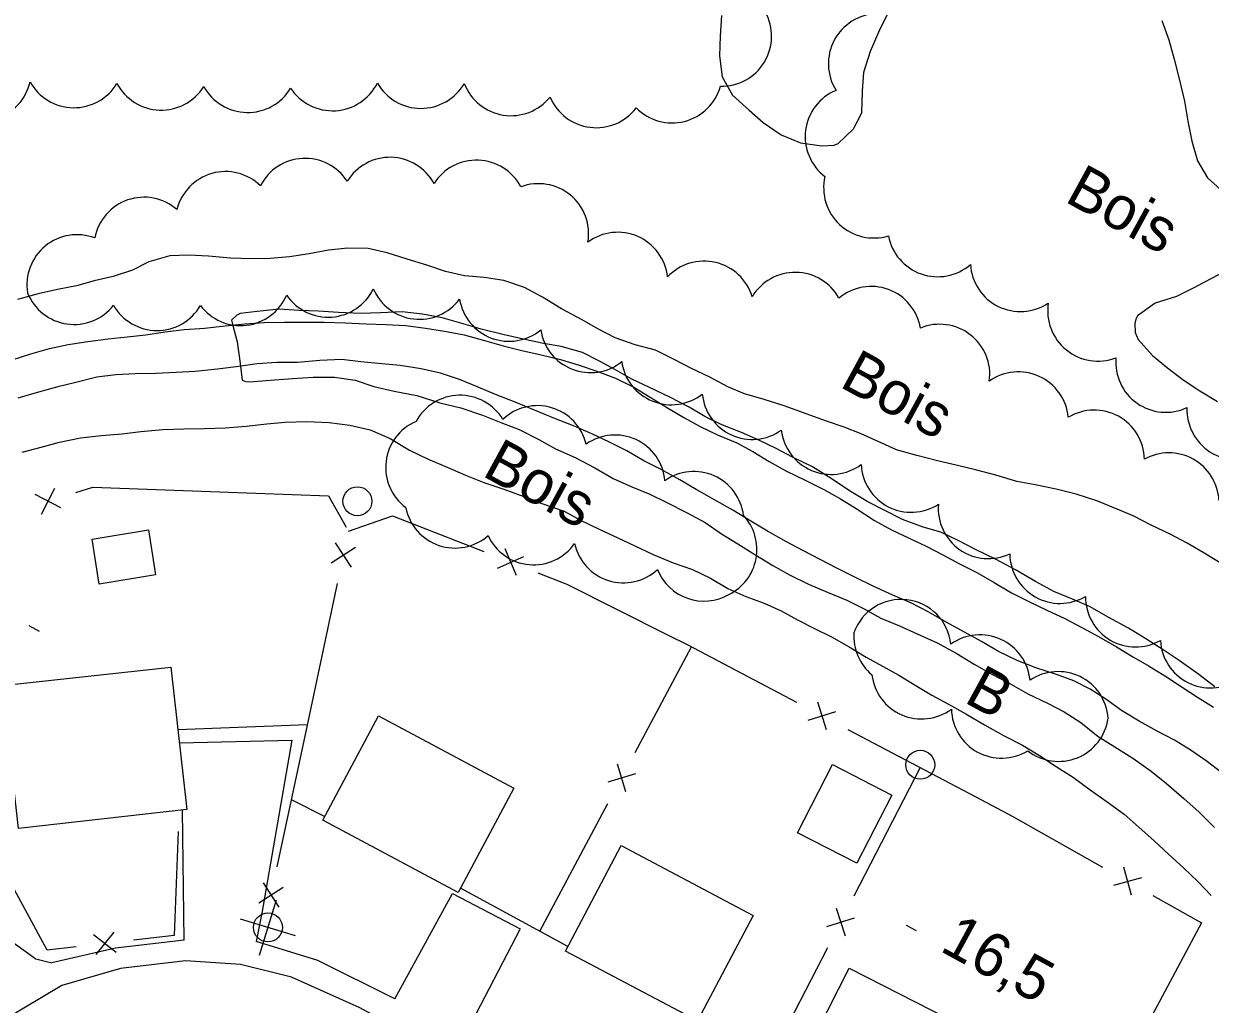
# Model space of a CAD drawing. Extents: x 219136 to 222520, y 5421589 to 5424530.
# Drawn here: x 220486.7 to 220568.6, y 5424061.3 to 5424129 of the extents above; entities that cross this region are included whole.
import ezdxf

# ---------------------------------------------------------------- set-up
doc = ezdxf.new("R2010")
doc.units = 0
for name, color, linetype in [('Level 19', 7, 'Continuous'), ('Level 2', 7, 'Continuous'), ('Level 21', 7, 'Continuous'), ('Level 3', 7, 'Continuous'), ('Level 31', 7, 'Continuous'), ('Level 36', 7, 'Continuous'), ('Level 37', 7, 'Continuous'), ('Level 4', 7, 'Continuous'), ('Level 44', 7, 'Continuous')]:
    doc.layers.add(name, color=color, linetype=linetype)

msp = doc.modelspace()

# ---------------------------------------------------------------- linework, layer by layer
at = {"layer": 'Level 19'}
for points in [[(220497.41, 5424079.37), (220505.18, 5424079.54), (220503.11, 5424067.61), (220502.72, 5424065.65)], [(220497.74, 5424065.73), (220497.63, 5424074.72)], [(220476.48, 5424066.51), (220479.86, 5424069.94), (220487.5, 5424064.45), (220488.59, 5424064.17)], [(220512.29, 5424061.68), (220516.28, 5424068.95), (220520.94, 5424066.53), (220517.29, 5424059.47)]]:
    msp.add_lwpolyline(points, dxfattribs=at)
at = {"layer": 'Level 2'}
for points in [[(220534.85, 5424129.57), (220534.75, 5424128.14), (220534.71, 5424126.8), (220534.9, 5424125.34), (220535.62, 5424124.07), (220536.76, 5424123.05), (220537.73, 5424122.19), (220538.97, 5424121.33), (220540.31, 5424120.78), (220541.79, 5424120.58), (220542.64, 5424120.62), (220542.91, 5424120.73), (220543.98, 5424121.74), (220544.55, 5424122.86), (220544.58, 5424124.36), (220544.68, 5424125.67), (220545.14, 5424127.11), (220545.74, 5424128.49), (220546.3, 5424129.61)], [(220565.27, 5424129.24), (220565.74, 5424127.89), (220566.11, 5424126.55), (220566.48, 5424125.12), (220566.83, 5424123.67), (220567.07, 5424122.27), (220567.33, 5424120.89), (220567.72, 5424119.53), (220568.43, 5424118.36), (220569.52, 5424117.38), (220570.52, 5424116.47), (220571.53, 5424115.73), (220572.04, 5424115.08), (220572.11, 5424114.81), (220572.12, 5424114.49), (220571.77, 5424113.28), (220571.34, 5424112.8), (220571, 5424112.63), (220569.84, 5424112.02), (220568.66, 5424111.4)], [(220553.79, 5424097.84), (220552.4, 5424098.22), (220551.15, 5424098.51), (220549.76, 5424098.83), (220548.34, 5424099.19), (220546.94, 5424099.6), (220545.68, 5424100.16), (220544.51, 5424100.7), (220543.32, 5424101.15), (220542.11, 5424101.58), (220540.69, 5424102.08), (220539.26, 5424102.6), (220537.8, 5424103.06), (220536.45, 5424103.45), (220535.29, 5424103.94), (220534.05, 5424104.61), (220532.78, 5424105.2), (220531.59, 5424105.83), (220530.29, 5424106.46), (220528.88, 5424106.85), (220527.5, 5424107.32), (220526.32, 5424107.94), (220525.22, 5424108.56), (220523.81, 5424109.32), (220522.49, 5424110.12), (220521.24, 5424110.79), (220519.81, 5424111.29), (220518.45, 5424111.49), (220517.11, 5424111.6), (220515.79, 5424111.89), (220514.49, 5424112.34), (220513.15, 5424112.76), (220511.77, 5424113.19), (220510.44, 5424113.49), (220509.04, 5424113.51), (220507.7, 5424113.37), (220506.37, 5424113.11), (220505.01, 5424112.92), (220503.68, 5424112.81), (220502.36, 5424112.77), (220500.95, 5424112.82), (220499.42, 5424112.95), (220498.06, 5424113.03), (220496.75, 5424112.98), (220495.31, 5424112.58), (220494.18, 5424111.99), (220492.83, 5424111.55), (220491.52, 5424111.25), (220490.31, 5424110.92), (220489, 5424110.66), (220487.65, 5424110.37), (220486.22, 5424109.97)], [(220568.66, 5424111.4), (220567.47, 5424110.78), (220566.27, 5424110.17), (220564.8, 5424109.71), (220563.58, 5424108.83), (220563.47, 5424108.6), (220563.4, 5424108.32), (220563.42, 5424107.7), (220563.64, 5424107.21), (220564.62, 5424106.11), (220565.66, 5424105.24), (220566.73, 5424104.42), (220567.9, 5424103.66), (220569.12, 5424102.93)], [(220552.39, 5424092.71), (220551.19, 5424093.32), (220550.01, 5424093.91), (220548.78, 5424094.25), (220547.36, 5424094.77), (220546.08, 5424095.43), (220544.96, 5424096), (220543.69, 5424096.76), (220542.42, 5424097.61), (220541.14, 5424098.42), (220539.75, 5424099.09), (220538.62, 5424099.69), (220537.42, 5424100.26), (220536.23, 5424100.78), (220534.83, 5424101.34), (220533.7, 5424101.88), (220532.62, 5424102.54), (220531.29, 5424103.23), (220529.88, 5424103.9), (220528.67, 5424104.46), (220527.54, 5424105.12), (220526.37, 5424105.74), (220525.25, 5424106.32), (220523.78, 5424106.73), (220522.55, 5424106.93), (220521.17, 5424107.23), (220519.75, 5424107.56), (220518.26, 5424107.92), (220516.86, 5424108.34), (220515.56, 5424108.7), (220514.21, 5424108.96), (220512.79, 5424109.12), (220511.29, 5424109.04), (220509.92, 5424109), (220508.39, 5424109.07), (220507.02, 5424109.16), (220505.69, 5424109.22), (220504.3, 5424109.29), (220502.78, 5424109.14), (220501.61, 5424109), (220501.38, 5424108.88), (220501.01, 5424108.54), (220501.08, 5424108.27), (220501.4, 5424107.04), (220501.6, 5424105.54), (220501.74, 5424104.39), (220501.99, 5424104.3), (220502.27, 5424104.29), (220503.69, 5424104.39), (220505.23, 5424104.52), (220506.66, 5424104.6), (220508.13, 5424104.6), (220509.56, 5424104.39), (220510.85, 5424103.97), (220512.25, 5424103.63), (220513.81, 5424103.35), (220515.4, 5424102.84), (220516.84, 5424102.48), (220518.34, 5424101.98), (220519.61, 5424101.48), (220520.87, 5424101), (220522.23, 5424100.3), (220523.39, 5424099.67), (220524.74, 5424099.06), (220526.1, 5424098.34)], [(220494.75, 5424100.85), (220496.27, 5424100.99), (220497.72, 5424101.05), (220499.14, 5424101.06), (220500.6, 5424101.12), (220502.03, 5424101.23), (220503.46, 5424101.38), (220504.72, 5424101.49), (220506.22, 5424101.55), (220507.75, 5424101.47), (220509.19, 5424101.3), (220510.59, 5424100.98), (220511.96, 5424100.37), (220513.3, 5424099.57), (220514.59, 5424098.94), (220515.91, 5424098.4), (220517.17, 5424097.84), (220518.43, 5424097.34), (220519.83, 5424096.87), (220521.21, 5424096.36), (220522.44, 5424095.89), (220523.98, 5424095.35), (220525.17, 5424094.72), (220526.41, 5424094.12), (220527.7, 5424093.51), (220528.86, 5424092.96), (220530.14, 5424092.37), (220531.51, 5424091.79), (220532.84, 5424091.33), (220534.1, 5424090.74), (220535.3, 5424090.02), (220536.54, 5424089.46), (220537.8, 5424089), (220538.97, 5424088.48), (220540.1, 5424087.86), (220541.24, 5424087.28), (220542.45, 5424086.68), (220543.68, 5424085.98), (220544.85, 5424085.28), (220545.98, 5424084.66), (220547.1, 5424084.04), (220548.24, 5424083.35), (220549.39, 5424082.66), (220550.54, 5424082.03), (220551.73, 5424081.36), (220553.01, 5424080.6), (220554.34, 5424079.88), (220555.64, 5424079.21), (220556.81, 5424078.48), (220557.97, 5424077.72), (220559.16, 5424076.96), (220560.32, 5424076.11), (220561.49, 5424075.29), (220562.66, 5424074.43), (220563.71, 5424073.51), (220564.72, 5424072.62), (220565.73, 5424071.67), (220566.78, 5424070.7), (220567.75, 5424069.78), (220568.68, 5424068.82)], [(220486.55, 5424099.42), (220487.87, 5424099.78), (220489.12, 5424100.11), (220490.58, 5424100.41), (220492.04, 5424100.57), (220493.45, 5424100.7), (220494.75, 5424100.85)], [(220526.1, 5424098.34), (220527.38, 5424097.61), (220528.65, 5424097.03), (220529.91, 5424096.54), (220531.04, 5424095.98), (220532.48, 5424095.25), (220533.73, 5424094.57), (220534.85, 5424093.8), (220535.99, 5424093.1), (220537.15, 5424092.37), (220538.4, 5424091.61), (220539.55, 5424090.96), (220540.87, 5424090.31), (220542.23, 5424089.73), (220543.51, 5424089.22), (220544.65, 5424088.63), (220545.85, 5424087.98), (220547.15, 5424087.43), (220548.36, 5424086.89), (220549.74, 5424086.26), (220551.07, 5424085.56), (220552.3, 5424084.79), (220553.52, 5424084.1), (220554.71, 5424083.48), (220556.02, 5424082.75), (220557.38, 5424082.1), (220558.53, 5424081.5), (220559.66, 5424080.77), (220560.87, 5424079.8), (220562.02, 5424079.08), (220563.27, 5424078.31), (220564.53, 5424077.4), (220565.58, 5424076.55), (220566.78, 5424075.51), (220567.85, 5424074.57), (220568.9, 5424073.52)], [(220569.37, 5424091.74), (220568.13, 5424092.5), (220567.02, 5424093.15), (220565.89, 5424093.74), (220564.49, 5424094.42), (220563.34, 5424095), (220562.19, 5424095.49), (220560.78, 5424096.07), (220559.35, 5424096.54), (220557.96, 5424096.87), (220556.51, 5424097.18), (220555.25, 5424097.41), (220553.79, 5424097.84)], [(220568.93, 5424083.23), (220567.82, 5424084.07), (220566.47, 5424085.04), (220565.35, 5424085.79), (220564.17, 5424086.55), (220562.96, 5424087.27), (220561.61, 5424088.01), (220560.27, 5424088.78), (220559.1, 5424089.28), (220557.8, 5424089.8), (220556.53, 5424090.49), (220555.17, 5424091.31), (220553.82, 5424092.02), (220552.39, 5424092.71)]]:
    msp.add_lwpolyline(points, dxfattribs=at)
at = {"layer": 'Level 21'}
for points in [[(220497.74, 5424065.73), (220492.99, 5424065.19), (220488.59, 5424064.17)], [(220512.29, 5424061.68), (220506.97, 5424064.33), (220502.72, 5424065.65)], [(220553.81, 5424039.07), (220553.73, 5424039.04), (220551.84, 5424039.1), (220549.83, 5424039.83), (220547.23, 5424041.1), (220509.83, 5424061.1), (220505.16, 5424063.19), (220501.63, 5424064.07), (220497.84, 5424064.31), (220493.34, 5424063.78), (220489.3, 5424062.62), (220485.23, 5424060.19), (220482.14, 5424057.35), (220479.4, 5424053.9), (220476.93, 5424049.58), (220459.72, 5424016.93), (220442.62, 5423984.31), (220432.48, 5423964.99)]]:
    msp.add_lwpolyline(points, dxfattribs=at)
at = {"layer": 'Level 3'}
for p, q in [((220487.02, 5424087.46), (220487.72, 5424087.08)), ((220547.61, 5424066.78), (220548.3, 5424066.4))]:
    msp.add_line(p, q, dxfattribs=at)
at = {"layer": 'Level 31'}
for points in [[(220495.77, 5424090.95), (220491.88, 5424090.32), (220491.38, 5424093.43), (220495.27, 5424094.06)], [(220485.2, 5424083.31), (220496.83, 5424084.59), (220497.92, 5424074.75), (220486.29, 5424073.46)], [(220511.16, 5424081.22), (220520.51, 5424076.23), (220516.66, 5424069.03), (220507.32, 5424074.02)], [(220540.1, 5424073.16), (220542.52, 5424077.86), (220546.62, 5424075.74), (220544.19, 5424071.05)], [(220533.2, 5424060.17), (220524.07, 5424064.99), (220527.92, 5424072.27), (220537.04, 5424067.45)], [(220549.09, 5424051.8), (220539.93, 5424056.46), (220543.67, 5424063.8), (220552.83, 5424059.13)]]:
    msp.add_lwpolyline(points, close=True, dxfattribs=at)
at = {"layer": 'Level 36'}
for p, q in [((220502.94, 5424064.71), (220504.11, 5424068.52)), ((220505.43, 5424066.03), (220501.62, 5424067.2))]:
    msp.add_line(p, q, dxfattribs=at)
for centre in [(220509.704, 5424096.037), (220548.584, 5424077.847), (220503.527, 5424066.623)]:
    msp.add_circle(centre, 1, dxfattribs=at)
at = {"layer": 'Level 37'}
for p, q in [((220487.88, 5424095.16), (220488.81, 5424096.94)), ((220489.23, 5424095.58), (220487.46, 5424096.51)), ((220507.89, 5424091.78), (220509.57, 5424092.87)), ((220508.18, 5424093.17), (220509.27, 5424091.49)), ((220519.38, 5424091.43), (220521.21, 5424092.23)), ((220520.7, 5424090.91), (220519.9, 5424092.75)), ((220542.1, 5424080.27), (220541.51, 5424082.18)), ((220540.85, 5424080.93), (220542.76, 5424081.52)), ((220528.25, 5424075.98), (220527.66, 5424077.9)), ((220528.91, 5424077.23), (220527, 5424076.65)), ((220563.18, 5424068.84), (220562.64, 5424070.77)), ((220561.95, 5424069.53), (220563.88, 5424070.07)), ((220502.89, 5424068.31), (220504.57, 5424069.4)), ((220503.19, 5424069.69), (220504.28, 5424068.01)), ((220542.78, 5424067.94), (220543.39, 5424066.03)), ((220542.13, 5424066.68), (220544.04, 5424067.29)), ((220491.48, 5424066.14), (220493.05, 5424064.9)), ((220492.89, 5424066.3), (220491.64, 5424064.74))]:
    msp.add_line(p, q, dxfattribs=at)
for points in [[(220490.26, 5424096.64), (220491.43, 5424097.01), (220500.19, 5424096.69)], [(220500.19, 5424096.69), (220507.71, 5424096.41), (220508.92, 5424094.25)], [(220509.08, 5424093.97), (220512.14, 5424095.03), (220518.43, 5424092.56)], [(220508.31, 5424090.37), (220506.23, 5424080.59)], [(220522.16, 5424091.1), (220524.17, 5424090.31), (220531.18, 5424086.8)], [(220531.18, 5424086.8), (220532.48, 5424086.15), (220540.04, 5424082.16)], [(220528.9, 5424078.7), (220532.78, 5424085.99)], [(220506.23, 5424080.6), (220497.31, 5424080.26)], [(220506.23, 5424080.59), (220504.15, 5424070.81)], [(220543.58, 5424080.29), (220552.42, 5424075.63)], [(220548.57, 5424077.66), (220544, 5424068.77)], [(220552.42, 5424075.63), (220554.97, 5424074.28), (220561.17, 5424070.79)], [(220505.14, 5424075.46), (220507.45, 5424074.27)], [(220522.31, 5424066.35), (220527.01, 5424075.17)], [(220497.33, 5424073.25), (220497.05, 5424066.07), (220494.25, 5424065.75)], [(220490.28, 5424065.29), (220488.27, 5424065.06), (220484.46, 5424072.07)], [(220524.24, 5424065.3), (220516.82, 5424069.33)], [(220564.65, 5424068.82), (220568.01, 5424066.93), (220565.11, 5424061.51)], [(220542.17, 5424065.21), (220538.38, 5424057.84)], [(220565.11, 5424061.51), (220560.38, 5424052.7)]]:
    msp.add_lwpolyline(points, dxfattribs=at)
at = {"layer": 'Level 4'}
for points in [[(220485.87, 5424105.81), (220487.16, 5424106.21), (220488.44, 5424106.59), (220489.73, 5424106.86), (220491.09, 5424107.08), (220492.48, 5424107.25), (220493.8, 5424107.39), (220495.1, 5424107.54), (220496.42, 5424107.73), (220497.75, 5424107.89), (220499.14, 5424107.99), (220500.58, 5424108.15), (220501.94, 5424108.28), (220503.27, 5424108.38), (220504.67, 5424108.41), (220506.05, 5424108.41), (220507.4, 5424108.41), (220508.85, 5424108.36), (220510.3, 5424108.29), (220511.68, 5424108.24), (220513.05, 5424108.17), (220514.41, 5424108), (220515.73, 5424107.79), (220517.08, 5424107.54), (220518.49, 5424107.14), (220519.77, 5424106.77), (220521.06, 5424106.45), (220522.4, 5424106.15), (220523.74, 5424105.82), (220525.02, 5424105.44), (220526.24, 5424105.01), (220527.54, 5424104.54), (220528.8, 5424103.91), (220529.92, 5424103.23), (220531.13, 5424102.48), (220532.24, 5424101.83), (220533.38, 5424101.19), (220534.63, 5424100.6), (220535.91, 5424100.07), (220537.02, 5424099.48), (220538.14, 5424098.78), (220539.34, 5424098.11), (220540.64, 5424097.5), (220541.91, 5424096.85), (220543.07, 5424096.2), (220544.15, 5424095.53), (220545.43, 5424094.72), (220546.6, 5424094.07), (220547.82, 5424093.49), (220549, 5424092.94), (220550.15, 5424092.35), (220551.34, 5424091.7), (220552.48, 5424091.13), (220553.69, 5424090.44)], [(220559.18, 5424083.65), (220557.98, 5424084.09), (220556.57, 5424084.54), (220555.27, 5424085.05), (220553.99, 5424085.66), (220552.81, 5424086.36), (220551.64, 5424087), (220550.42, 5424087.68), (220549.18, 5424088.39), (220547.92, 5424089.03), (220546.69, 5424089.56), (220545.37, 5424090.15), (220544.06, 5424090.8), (220542.86, 5424091.4), (220541.66, 5424092.01), (220540.51, 5424092.62), (220539.34, 5424093.25), (220538.04, 5424093.97), (220536.87, 5424094.66), (220535.64, 5424095.43), (220534.36, 5424096.13), (220533.11, 5424096.84), (220531.97, 5424097.52), (220530.65, 5424098.25), (220529.5, 5424098.84), (220528.32, 5424099.53), (220527.12, 5424100.13), (220525.89, 5424100.69), (220524.62, 5424101.25), (220523.28, 5424101.78), (220521.93, 5424102.32), (220520.61, 5424102.87), (220519.24, 5424103.41), (220518.04, 5424103.92), (220516.76, 5424104.44), (220515.45, 5424104.88), (220514.1, 5424105.19), (220512.65, 5424105.41), (220511.4, 5424105.52), (220509.94, 5424105.67), (220508.63, 5424105.82), (220507.12, 5424105.76), (220505.57, 5424105.61), (220504.15, 5424105.62), (220502.79, 5424105.52), (220501.34, 5424105.32), (220500.05, 5424105.17), (220498.51, 5424105), (220497.18, 5424104.92), (220495.75, 5424104.85), (220494.35, 5424104.83), (220493.02, 5424104.77), (220491.71, 5424104.6), (220490.26, 5424104.24), (220489.01, 5424103.94), (220487.68, 5424103.57), (220486.25, 5424103.16)], [(220553.69, 5424090.44), (220554.89, 5424089.72), (220556.12, 5424089.09), (220557.33, 5424088.51), (220558.57, 5424087.95), (220559.74, 5424087.33), (220560.9, 5424086.7), (220562.13, 5424086), (220563.3, 5424085.28), (220564.39, 5424084.66), (220565.59, 5424083.93), (220566.68, 5424083.2), (220567.72, 5424082.51), (220568.83, 5424081.83)], [(220569.41, 5424077.29), (220568.32, 5424078.13), (220567.23, 5424078.89), (220566.13, 5424079.54), (220564.95, 5424080.16), (220563.69, 5424080.86), (220562.49, 5424081.6), (220561.4, 5424082.38), (220560.32, 5424083.06), (220559.18, 5424083.65)]]:
    msp.add_lwpolyline(points, dxfattribs=at)
at = {"layer": 'Level 44'}
for centre, start, end in [((220534.85, 5424128.15), 268.80902, 28.80902), ((220545.7, 5424126.242), 91.98676, 211.98676), ((220483.722, 5424125.766), 227.11048, 347.11048), ((220490.129, 5424126.672), 208.98219, 328.98219), ((220496.16, 5424126.506), 207.86755, 327.86755), ((220507.987, 5424126.46), 213.33473, 333.33473), ((220514.09, 5424126.624), 209.74957, 329.74957), ((220520.316, 5424126.122), 201.02992, 321.02992), ((220502.124, 5424126.342), 208.97303, 328.97303), ((220531.443, 5424125.624), 224.29932, 344.29932), ((220544.097, 5424121.211), 112.66534, 232.66534), ((220526.2, 5424125.293), 202.92585, 322.92585), ((220506.096, 5424116.247), 32.95573, 152.95573), ((220511.956, 5424116.32), 28.47441, 148.47441), ((220517.933, 5424116.126), 27.81439, 147.81439), ((220500.597, 5424115.337), 45.83456, 165.83456), ((220545.371, 5424117.677), 166.99989, 286.99989), ((220522.214, 5424114.5), 350.5733, 110.5733), ((220494.972, 5424113.565), 49.14106, 169.14106), ((220490.343, 5424110.978), 69.2558, 189.2558), ((220527.684, 5424111.142), 6.33976, 126.33976), ((220549.788, 5424115.004), 190.63755, 310.63755), ((220533.654, 5424109.155), 16.83746, 136.83746), ((220539.942, 5424108.38), 29.12348, 149.12348), ((220555.501, 5424112.6), 183.73053, 303.73053), ((220545.188, 5424107.406), 9.84269, 129.84269), ((220490.14, 5424111.709), 201.83273, 321.83273), ((220501.635, 5424111.63), 216.86502, 336.86502), ((220507.688, 5424112.213), 214.13958, 334.13958), ((220513.988, 5424112.067), 203.21606, 323.21606), ((220495.868, 5424111.292), 209.83758, 329.83758), ((220520.182, 5424110.549), 189.23661, 309.23661), ((220560.847, 5424109.183), 171.08658, 291.08658), ((220525.798, 5424108.384), 188.60623, 308.60623), ((220549.918, 5424104.795), 352.35493, 112.35493), ((220565.544, 5424105.643), 174.90123, 294.90123), ((220531.389, 5424106.167), 188.13504, 308.13504), ((220555.358, 5424101.51), 5.38473, 125.38473), ((220516.794, 5424099.893), 31.30751, 151.30751), ((220536.977, 5424103.771), 185.43957, 305.43957), ((220522.135, 5424099.177), 13.43598, 133.43598), ((220560.6, 5424098.871), 1.18931, 121.18931), ((220570.464, 5424102.364), 177.7335, 297.7335), ((220515.122, 5424098.373), 113.24581, 233.24581), ((220527.499, 5424097.15), 5.14798, 125.14798), ((220542.425, 5424101.356), 186.74592, 306.74592), ((220565.753, 5424095.919), 3.23224, 119.18513), ((220547.958, 5424098.743), 182.69794, 302.69794), ((220532.941, 5424094.626), 7.26317, 125.09121), ((220516.447, 5424096.272), 191.23417, 311.23417), ((220553.282, 5424095.548), 175.36695, 295.36695), ((220533.835, 5424092.71), 296.11259, 42.80834), ((220521.878, 5424095.115), 204.71298, 324.71298), ((220528.086, 5424093.87), 192.59624, 312.59624), ((220558.23, 5424092.45), 180.52961, 300.52961), ((220533.646, 5424092.609), 201.85831, 299.66792), ((220547.258, 5424085.796), 6.24759, 160.4124), ((220563.454, 5424089.445), 179.64659, 299.64659), ((220547.451, 5424086.732), 176.2611, 230.33081), ((220552.713, 5424083.353), 5.48937, 125.48937), ((220568.627, 5424086.615), 182.99948, 302.99948), ((220548.68, 5424084.474), 186.77554, 306.30993), ((220558.105, 5424080.817), 4.133, 124.133), ((220554.194, 5424081.768), 181.41303, 301.41303), ((220558.129, 5424081.544), 232.07435, 352.07435)]:
    msp.add_arc(centre, 3.464, start, end, dxfattribs=at)

# ---------------------------------------------------------------- texts
at = {"layer": 'Level 3'}
msp.add_text('16,5', height=3, rotation=331.383, dxfattribs=at).set_placement((220549.85, 5424065.04))
at = {"layer": 'Level 44'}
for s, p in [('Bois', (220558.47, 5424116.77)), ('Bois', (220542.92, 5424103.99)), ('Bois', (220518.23, 5424097.84)), ('B', (220551.52, 5424082.21))]:
    msp.add_text(s, height=3, rotation=331.35475, dxfattribs=at).set_placement(p)

doc.saveas('drawing.dxf')
